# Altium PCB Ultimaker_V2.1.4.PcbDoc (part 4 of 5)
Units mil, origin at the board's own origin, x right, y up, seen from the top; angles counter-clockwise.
Board outline 6889.76 x 3110.24 mil, 4 copper layers (top, signal, Power, bot (thermal)), stack 67.717 mil thick; 574 components, 252 nets, 1322 pads, 511 vias.
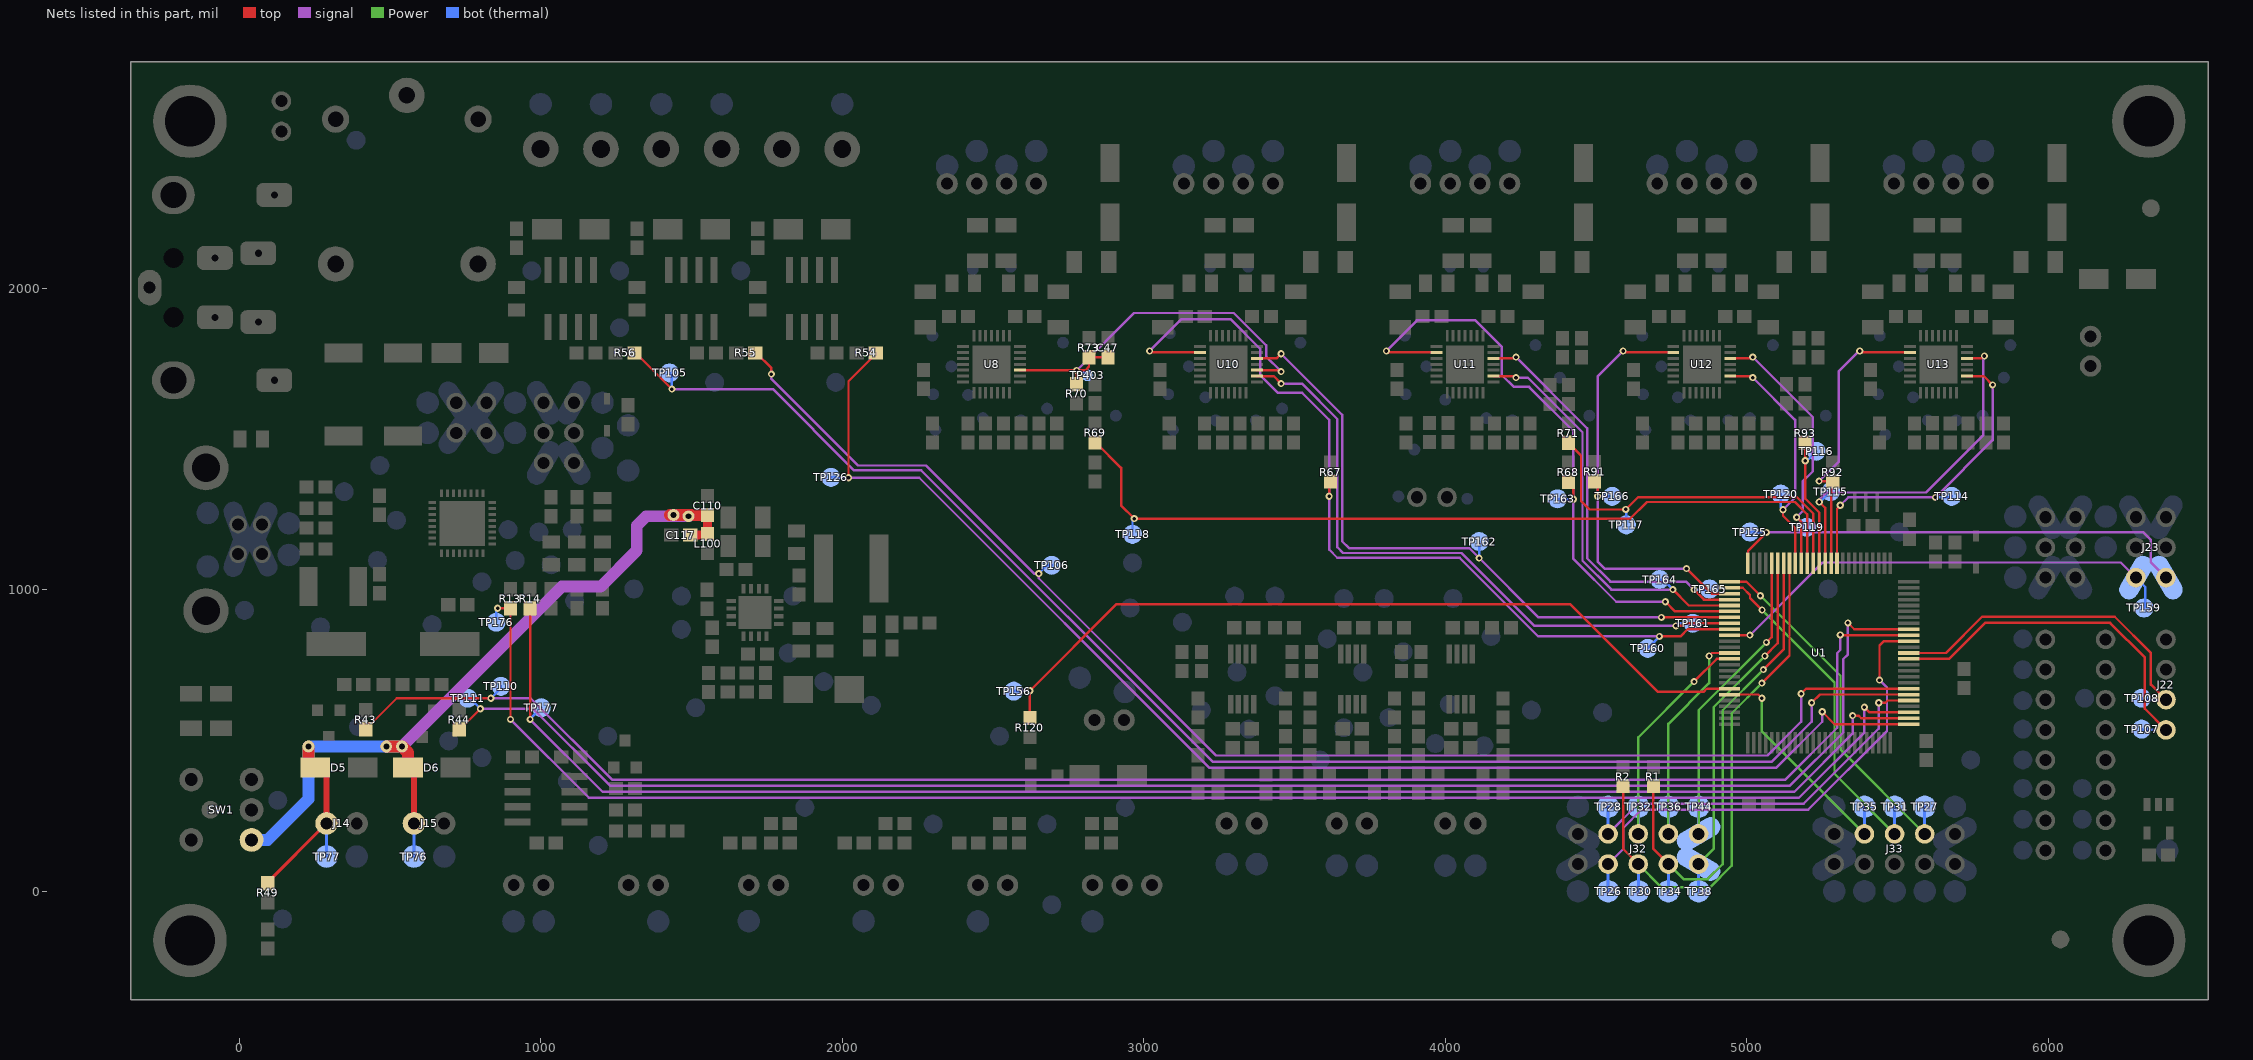
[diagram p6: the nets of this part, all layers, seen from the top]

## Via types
v1: diameter 23.62, hole 11.81, top to bot (thermal), tented bottom, 172 vias
v2: diameter 23.62, hole 11.81, top to bot (thermal), tented both sides, 104 vias
v3: diameter 39.37, hole 19.68, top to bot (thermal), tented bottom, 88 vias
v4: diameter 25.98, hole 12.99, top to bot (thermal), tented bottom, 58 vias
v5: diameter 23.62, hole 11.81, top to bot (thermal), 46 vias
v6: diameter 39.37, hole 19.68, top to bot (thermal), tented both sides, 43 vias

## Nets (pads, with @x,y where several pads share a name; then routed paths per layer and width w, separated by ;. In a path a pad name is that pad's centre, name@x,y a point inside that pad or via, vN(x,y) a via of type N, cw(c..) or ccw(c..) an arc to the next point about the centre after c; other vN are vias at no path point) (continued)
PC0: R91.1 TP166.1 U1.53 U12.2 | length 1469.7
  top w8: v1(4505,1309.88) R91.1@4505,1349.88 ; v1@4590.27,1786.76 U12.2@4756.14,1786.76 ; v1(4800,1070) 4883.15,986.85 U1.53@4942.76,986.85
  signal w8: v1(4589.64,1791.39) 4505,1706.76 v1(4505,1309.88) 4505,1093.03 4528.03,1070 v1(4800,1070)
  bot (thermal) w8: v1(4505,1309.88) 4552.8,1309.88 TP166.1@4553.39,1309.29
PC1: TP165.1 U1.54 U11.19 | length 1422.5
  top w8: U11.19@4160.12,1767.08 4230.32,1767.08 v1(4234.64,1771.39) ; v1(4825,1000) 4857.83,967.17 U1.54@4942.76,967.17
  signal w8: v1(4234.64,1771.39) 4471,1535.03 4471,1103.4 4547.48,1026.92 4798.08,1026.92 v1(4825,1000)
  bot (thermal) w8: v1(4825,1000) 4874.02,1000 TP165.1@4876.22,1002.2
PC2: TP164.1 U1.55 U11.16 | length 1405.3
  top w8: U11.16@4160.12,1708.02 4230.01,1708.02 v1(4234.64,1703.39) ; v1(4755,1000) 4807.52,947.48 U1.55@4942.76,947.48
  signal w8: v1(4234.64,1703.39) 4273.46,1703.39 4455,1521.85 4455,1095.78 4550.78,1000 v1(4755,1000)
  bot (thermal) w8: TP164.1@4710.87,1033.7 4721.3,1033.7 v1(4755,1000)
PC3: R68.1 TP163.1 U1.56 U11.2 | length 2182.5
  top w8: v1@3805.27,1786.76 U11.2@3971.14,1786.76 ; R68.1@4420,1354.88 4416.5,1358.39 4405,1358.39 4425,1338.39 v1(4425,1299.88) ; v1(4730,960) 4762.2,927.8 U1.56@4942.76,927.8
  signal w8: v1@3804.64,1791.52 3906,1892.88 4100,1892.88 4187,1805.88 4187,1712.88 4227.49,1672.39 4277.89,1672.39 4425,1525.29 v1(4425,1299.88) 4425,1102.16 4567.16,960 v1(4730,960)
  bot (thermal) w8: TP163.1@4373.82,1299.88 v1(4425,1299.88)
  other v1: 3804.64,1791.39
PC4: TP162.1 U1.57 U10.19 | length 2234.9
  top w8: U10.19@3375.12,1767.08 3440.32,1767.08 3450.64,1777.39 v1@3455.64,1777.39 ; v1(4716.69,908.11) U1.57@4942.76,908.11
  signal w8: v1(3455.64,1782.39) 3657.97,1580.06 3657.97,1160.53 3680.84,1137.66 4079.35,1137.66 v5(4112.44,1104.57) 4308.9,908.11 v1(4716.69,908.11)
  bot (thermal) w8: v5(4112.44,1104.57) TP162.1@4112.44,1159.69
PC5: TP161.1 U1.58 U10.16 | length 2222.6
  top w8: U10.16@3375.12,1708.02 3431.01,1708.02 v1(3455.64,1683.39) ; v1(4765,880) 4785.2,880 4793.62,888.43 U1.58@4942.76,888.43
  signal w8: v1(3455.64,1683.39) 3524.64,1683.39 3641.97,1566.06 3641.97,1141.09 3661.4,1121.66 4054.11,1121.66 4295.77,880 v1(4765,880)
  bot (thermal) w8: v1(4765,880) 4773.43,888.43 TP161.1@4821.1,888.43
PC6: R67.1 TP160.1 U1.59 U10.2 | length 2983.8
  top w8: v1@3020.27,1786.76 U10.2@3186.14,1786.76 ; v1(3615,1309.88) R67.1@3615,1353.39 ; v1(4710,845) 4715,850 4720,845 4780,845 4803.74,868.74 U1.59@4942.76,868.74
  signal w8: v1(3019.64,1791.39) 3125.64,1897.39 3287.64,1897.39 3386.07,1798.97 3386.07,1711.97 3445.64,1652.39 3525.64,1652.39 3615,1563.03 v1(3615,1309.88) 3615,1132.63 3641.97,1105.66 4047.48,1105.66 4308.14,845 v1(4710,845)
  bot (thermal) w8: TP160.1@4671.5,806.5 v1(4710,845)
PC7: J23.2@6290,1040 J23.5 TP159.1 U1.60 | length 1583.1
  top w8: U1.60@4942.76,849.06 v1(5010,849.06)
  signal w8: v1(5010,849.06) 5250.94,1090 6240,1090 J23.5@6290,1040
  bot (thermal) w8: J23.5@6290,1040 6321.1,1008.9 6321.1,943.15 TP159.1@6317.17,939.21
PD7: J23.4@6390,1040 J23.6 TP125.1 U1.50 | length 1624.6
  top w8: U1.50@5003.78,1077.24 U1.50@5003.78,1087.24 5003.78,1128.78 v1(5065,1190)
  signal w8: v1(5065,1190) 6315,1190 6340,1165 6340,1090 J23.6@6390,1040
  bot (thermal) w8: TP125.1@5010.08,1191.18 5011.26,1190 v1(5065,1190)
PE0: R14.2 TP177.1 U1.2 | length 5237.6
  top w8: v1(965,570) R14.2@965,938.5 ; v1(5350.64,582.51) 5370.64,582.51 5379.68,573.46 U1.2@5537.24,573.46
  signal w8: v1(965,570) 1205,330 5158.13,330 5350.64,522.51 v1(5350.64,582.51)
  bot (thermal) w8: v1(965,570) 965,571.3 TP177.1@1002.2,608.5
PE1: R13.2 TP176.1 U1.3 | length 5384.6
  top w8: v2(857.24,938.5) R13.2@900,938.5 v1(900,570) ; v1(5390,610) 5406.85,593.15 U1.3@5537.24,593.15
  signal w8: v1(900,570) 1160,310 5173.13,310 5390,526.87 v1(5390,610)
  bot (thermal) w8: TP176.1@852.6,891.97 852.6,933.86 v2(857.24,938.5)
PE3: J32.7 TP28.1 U1.5 | length 1320.7
  top w8: v1(5437.5,625) 5460,625 5467.52,632.52 U1.5@5537.24,632.52
  signal w8: J32.7@4540,190 4640,290 5188.13,290 5437.5,539.37 v1(5437.5,625)
  bot (thermal) w10: J32.7@4540,190 TP28.1@4540,280
PE4: R56.1 TP105.1 U1.6 | length 4965.9
  top w8: R56.1@1317.5,1782.5 v1(1435,1665) ; v1(5215,625) 5242.2,652.2 U1.6@5537.24,652.2
  signal w8: v1(1435,1665) 1770,1665 2039.35,1395.65 2262.3,1395.65 3227.95,430 5083.13,430 5215,561.87 v1(5215,625)
  bot (thermal) w8: TP105.1@1427.4,1718.74 1435,1711.14 v1(1435,1665)
PE5: R55.1 TP106.1 U1.7 | length 4615.5
  top w8: R55.1@1711.5,1785 1715,1785 1765,1735 v1(1765,1715) ; v1(5180,655) 5196.89,671.89 U1.7@5537.24,671.89
  signal w8: v1@1765,1710 v1(1765,1715) 1765,1698.5 2051.85,1411.65 2277.8,1411.65 2636.06,1053.39 v5(2651.81,1053.39) 2651.81,1037.64 3239.45,450 5068.13,450 5180,561.87 v1(5180,655)
  bot (thermal) w8: v5(2651.81,1053.39) 2679.37,1080.94 TP106.1@2695.12,1080.94
PG0: J33.3 TP27.1 U1.51 | length 1239.4
  top w8: U1.51@4955,1026.22 U1.51@4942.76,1026.22 4998.78,1026.22 v1(5045,980)
  Power w8: v1(5045,980) 5310.64,714.36 5310.64,469.36 J33.3@5590,190
  bot (thermal) w10: J33.3@5590,190 TP27.1@5590,280
PG1: J33.5 TP31.1 U1.52 | length 1158.9
  top w8: U1.52@4942.76,1006.54 4986.61,1006.54 5010.64,982.51 5010.64,972.51 v1(5050.64,932.51)
  Power w8: v1(5050.64,932.51) 5290.64,692.51 5290.64,389.36 J33.5@5490,190
  bot (thermal) w10: J33.5@5490,190 TP31.1@5490,280
PG2: J33.7 TP35.1 U1.70 | length 793.1
  top w8: U1.70@4942.76,652.2 5037.8,652.2 v1(5050,640)
  Power w8: v1(5050,640) 5050,530 J33.7@5390,190
  bot (thermal) w10: J33.7@5390,190 TP35.1@5390,280
PG5: R54.1 TP126.1 U1.1 | length 4538
  top w8: v1(2021,1371) 2021,1691 R54.1@2112.5,1782.5 ; R54.1@2111.5,1785 R54.1@2113.25,1783.25 ; v1(5250,595) 5291.22,553.78 U1.1@5537.24,553.78
  signal w8: v1(2021,1371) 2255.46,1371 3216.46,410 5098.13,410 5250,561.87 v1(5250,595)
  bot (thermal) w8: TP126.1@1962.83,1372.28 2019.72,1372.28 v1(2021,1371)
PH3: J32.8 TP26.1 U1.15 | length 1635.7
  top w8: v1(5440,700) 5440,815 5454.37,829.37 U1.15@5537.24,829.37
  signal w8: J32.8@4540,90 4590,140 4590,210 4650,270 5203.13,270 5465,531.87 5465,675 v1(5440,700)
  bot (thermal) w10: TP26.1@4540,0 J32.8@4540,90
PH4: R43.1 TP110.1 U1.16 | length 5698.4
  top w8: R43.1@420,537.01 523,640 v1(835,640) ; v1@5310,849.06 U1.16@5537.24,849.06
  signal w8: v1(835,640) 966.77,640 1236.77,370 5128.13,370 5300,541.87 5300,790 5310,800 v1(5310,850)
  bot (thermal) w8: v1(835,640) 868.35,673.35 TP110.1@868.35,679.37
PH5: R44.1 TP111.1 U1.17 | length 5433.8
  top w8: R44.1@732.01,537.01 v1(800,605) ; v1(5335,890) 5356.26,868.74 U1.17@5537.24,868.74
  top w10: R44.1@730,537.01 R44.1@732.01,537.01
  signal w8: v1(800,605) 975,605 1230,350 5143.13,350 5320,526.87 5320,770 5335,785 v1(5335,890)
  bot (thermal) w8: TP111.1@765,640 v1(800,605) v1@793.11,605
PJ6: R120.1 TP156.1 U1.69 | length 2709
  top w8: R120.1@2622.29,574.17 v5(2622.29,664.72) 2909.69,952.12 4413.62,952.12 4704.96,660.78 4855.97,660.78 4867.08,671.89 U1.69@4942.76,671.89
  bot (thermal) w8: TP156.1@2569.13,663.62 2570.23,664.72 v5(2622.29,664.72)
PL0: TP114.1 U1.35 U13.16 | length 1133.3
  top w8: U1.35@5299.06,1087.24 5299.06,1268.06 v1@5310.5,1279.5 ; U13.16@5730.12,1708.02 5785.86,1708.02 v1(5815,1678.88)
  signal w8: v1(5310,1280) 5336.2,1306.2 v5(5625.32,1306.2) 5815,1495.88 v1(5815,1678.88)
  bot (thermal) w8: v5(5625.32,1306.2) 5676.28,1306.2 TP114.1@5679.37,1309.29 ; v1(5815,1678.88) v1@5821.59,1678.88
PL1: R92.1 U1.36 U13.2 | length 970
  top w8: v1(5240,1359.88) R92.1@5285,1359.88 ; U1.36@5279.37,1087.24 5279.37,1352.76 R92.1@5285,1358.39 ; v1@5375.27,1786.76 U13.2@5541.14,1786.76
  signal w8: v1(5240,1359.88) 5305.35,1425.24 5305.35,1724.93 v1@5369.99,1789.57 ; v1@5374.63,1791.08 v1@5376.14,1789.57
  other v1: 5374.64,1791.39
PL2: TP115.1 U1.37 U13.19 | length 1204.4
  top w8: v5(5240.4,1290.7) 5259.68,1271.41 U1.37@5259.68,1087.24 U1.37@5260,1087.56 ; U13.19@5730.12,1767.08 v1@5779.77,1767.08
  signal w8: v5@5240.4,1298.57 5264.02,1322.2 5594.73,1322.2 5783.7,1511.17 v1@5783.7,1771.02
  bot (thermal) w8: v5(5240.4,1290.7) 5243.46,1290.7 TP115.1@5277.8,1325.04
  other v1: 5787.64,1774.95
PL3: R93.1 TP116.1 U1.38 | length 469.8
  top w8: R93.1@5193.64,1487.9 v2(5193.64,1427.4) 5193.64,1302.03 5240,1255.66 U1.38@5240,1087.24
  bot (thermal) w8: v2(5193.64,1427.4) 5199.05,1427.4 TP116.1@5230.55,1458.9
PL4: R71.1 TP117.1 U1.39 | length 1251.4
  top w8: R71.1@4405.64,1488.39 4406.49,1488.39 4450,1444.88 4450,1294.57 4478.58,1265.98 v2(4598.56,1265.98) 4639.28,1306.7 5165.93,1306.7 5220.32,1252.31 U1.39@5220.32,1087.24
  bot (thermal) w8: v2(4598.56,1265.98) 4600.63,1263.92 TP117.1@4600.63,1214.8
PL5: R69.1 TP118.1 U1.40 | length 2799.6
  top w8: R69.1@2835.64,1488.39 2840.64,1488.39 2925,1404.03 2925,1279.33 v2(2968.74,1235.58) 4613.54,1235.58 4668.65,1290.7 5159.3,1290.7 5200,1250 5200,1087.87 U1.40@5200.63,1087.24
  bot (thermal) w8: TP118.1@2962.83,1183.31 2962.83,1229.67 v2(2968.74,1235.58)
PL6: TP119.1 U1.41 U12.19 | length 919.5
  top w8: U12.19@4945.12,1767.08 5015.32,1767.08 v1(5019.64,1771.39) ; v2(5165,1240) 5180.94,1224.06 U1.41@5180.94,1087.24
  signal w8: v1(5019.64,1771.39) 5218.74,1572.29 5218.74,1391.97 5185,1358.23 5185,1260 v2(5165,1240)
  bot (thermal) w8: v2(5165,1240) 5165.98,1240 TP119.1@5199.06,1206.93
PL7: TP120.1 U1.42 U12.16 | length 833.1
  top w8: U12.16@4945.12,1708.02 v1@5015.01,1708.02 ; v2(5120,1265) 5120,1245 5161.26,1203.74 U1.42@5161.26,1087.24
  signal w8: v1(5019.64,1703.39) 5160,1563.03 5160,1305 v2(5120,1265)
  bot (thermal) w8: TP120.1@5112.44,1317.17 5112.44,1272.56 v2(5120,1265)
RXD1: J32.2 TP38.1 U1.45 | length 1195.9
  top w8: v1(5060,780) 5102.2,822.2 U1.45@5102.2,1087.24
  Power w8: J32.2@4840,90 4890,140 4890,610 v1(5060,780)
  bot (thermal) w10: TP38.1@4840,0 J32.2@4840,90
RXD2: J22.4 TP107.1 U1.12 | length 1230.8
  top w8: U1.12@5537.24,770.31 5670.32,770.31 5790,890 6205,890 6320,775 6320,605 J22.4@6390,535
  bot (thermal) w8: TP107.1@6309.29,537.64 6311.93,535 J22.4@6390,535
RXD3: J32.3 TP36.1 U1.63 | length 807.8
  top w8: v1(4875,780) 4885,790 U1.63@4942.76,790
  Power w8: J32.3@4740,190 4740,555 4875,690 v1(4875,780)
  bot (thermal) w10: J32.3@4740,190 TP36.1@4740,280
SCL: J32.6 R2.2 TP30.1 U1.43 | length 1822.9
  top w8: R2.2@4590,348.5 4590,140 J32.6@4640,90 ; v1(5050,690) 5141.57,781.57 U1.43@5141.57,1087.24
  Power w8: J32.6@4640,90 4717.49,12.51 4877.51,12.51 4950,85 4950,590 v1(5050,690)
  bot (thermal) w10: TP30.1@4640,0 J32.6@4640,90
SDA: J32.4 R1.2 TP34.1 U1.44 | length 1671.5
  top w8: R1.2@4690,348.5 4690,140 J32.4@4740,90 ; v1(5055,735) 5121.89,801.89 U1.44@5121.89,1087.24
  Power w8: J32.4@4740,90 4790,40 4870,40 4920,90 4920,600 v1(5055,735)
  bot (thermal) w10: TP34.1@4740,0 J32.4@4740,90
TXD1: J32.1 TP44.1 U1.46 | length 1087.7
  top w8: v1(5065,825) 5082.52,842.52 U1.46@5082.52,1087.24
  Power w8: J32.1@4840,190 4840,600 v1(5065,825)
  bot (thermal) w10: J32.1@4840,190 TP44.1@4840,280
TXD2: J22.3 TP108.1 U1.13 | length 1160.7
  top w8: U1.13@5537.24,790 5660,790 5780,910 6220,910 6340,790 6340,685 J22.3@6390,635
  bot (thermal) w8: TP108.1@6309.29,640 6314.29,635 J22.3@6390,635
TXD3: J32.5 TP32.1 U1.64 | length 820.6
  top w8: v1(4825,695) 4900.32,770.31 U1.64@4942.76,770.31
  Power w8: J32.5@4640,190 4640,510 v1(4825,695)
  bot (thermal) w10: J32.5@4640,190 TP32.1@4640,280
VCC/2: C110.2 C117.2 D5.2 D6.2 J14.1 J15.1 L100.1 R49.2 SW1.1 TP76.1 TP77.1 | length 3463.4
  top w10: R49.2@91.5,26.5 J14.1@290,225 J14.1@290,230
  top w20: D5.2@252.52,410 290,410 J14.1@290,230 ; v3(488.19,480.31) v3@488.5,480 ; D6.2@560,410 580,390 J15.1@580,230
  top w30: C117.2@1496.06,1181.1 1550.09,1181.1 L100.1@1553.39,1184.4 C110.2@1553.39,1247.39
  top w40: D5.2@230,410 v3(230,480) ; v3@488.5,480 540,480 560,460 D6.2@560,410 ; v6@1429.13,1247.39 C110.2@1553.39,1247.39
  signal w39.37: v3(488.19,480.31) v3@540,480.31 ; v3@540.31,480.31 1070,1010 1198.98,1010 1318.9,1129.92 1318.9,1212.6 1349.76,1243.46 1441.18,1243.46 v6(1490.4,1243.46)
  bot (thermal) w10: TP77.1@290,115 J14.1@290,230 ; TP76.1@580,115 J15.1@580,230
  bot (thermal) w39.37: SW1.1@41.26,170 95,170 230,305 v3(230,480) v3@539.69,480
  other v3: 539.69,480.31
  other v6: 1440.94,1247.39
YREF: C47.2 R70.2 R73.2 TP403.1 U8.17 U10.17 | length 1356
  top w8: U8.17@2590.13,1727.71 2777.64,1727.71 v1(2777.64,1727.39) ; R70.2@2777.64,1685.89 v1(2777.64,1727.39) ; R73.2@2818.47,1771.02 2818.47,1739.52 2806.35,1727.39 v1(2777.64,1727.39) ; R73.2@2818.47,1771.39 C47.2@2881.46,1771.39 ; U10.17@3375.12,1727.71 3448.32,1727.71 v1@3454.64,1721.39
  signal w8: v1(2777.64,1727.39) 2967.64,1917.39 3298.74,1917.39 3405.75,1810.39 3405.75,1773.28 v1@3454.64,1724.39 ; v1@3454.64,1721.39 v1@3454.64,1724.39 ; v1(3455.64,1723.39) v1@3454.64,1724.39
  bot (thermal) w8: v1(2777.64,1727.39) 2796.7,1727.39 TP403.1@2813.23,1710.87
pads on no net: Fid1. Fid2. Fid3. J18.0 K1.5 SP1.0 SP2.0 SP3.0 SP4.0 SW1.0 SW1.3 U1.4 U1.8 U1.9 U1.14 U1.18 U1.23 U1.24 U1.25 U1.27 U1.28 U1.29 U1.47 U1.48 U1.49 U1.65 U1.66 U1.67 U1.68 U1.76 U1.79 U2.5 U2.6 U2.7 U2.12 U2.14 U2.22 U2.23 U2.25 U2.26 U7.7 U8.7 U8.20 U8.25 U9.4 U10.7 U10.20 U10.25 U11.7 U11.20 U11.25 U12.7 U12.20 U12.25 U13.7 U13.20 U13.25

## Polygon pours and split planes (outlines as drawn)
+5V on Power "+5V" (solid, remove dead copper, pour order 16): 6500,2390 6170,2390 6170,2720 0,2720 0,2390 -330,2390 -330,0 0,0 0,-330 6170,-330 6170,0 6500,0
GND on signal "+5V" (solid, remove dead copper, pour order 15): 6500,2390 6170,2390 6170,2720 0,2720 0,2390 -330,2390 -330,0 0,0 0,-330 6170,-330 6170,0 6500,0
+24V on signal "Top Layer-No Net 1" (solid, pour order 17): 5413.63,2092.39 5413.63,1935.39 5580.63,1935.39 5580.63,1967.39 5455.63,2092.39 5413.63,2092.39
+24V on signal "Top Layer-No Net 1" (solid, pour order 22): 5690.63,1935.39 5690.63,1967.39 5815.63,2092.39 5905.98,1966.77 5815.63,1935.39
+24V on signal "Top Layer-No Net 1" (solid, pour order 18): 4628.63,2092.39 4628.63,1935.39 4795.63,1935.39 4795.63,1967.39 4670.63,2092.39 4628.63,2092.39
+24V on signal "Top Layer-No Net 1" (solid, pour order 23): 4905.63,1935.39 4905.63,1967.39 5030.63,2092.39 5120.98,1966.77 5030.63,1935.39
+24V on signal "Top Layer-No Net 1" (solid, pour order 19): 3843.63,2092.39 3843.63,1935.39 4010.63,1935.39 4010.63,1967.39 3885.63,2092.39 3843.63,2092.39
+24V on signal "Top Layer-No Net 1" (solid, pour order 24): 4120.63,1935.39 4120.63,1967.39 4245.63,2092.39 4335.98,1966.77 4245.63,1935.39
+24V on signal "Top Layer-No Net 1" (solid, pour order 20): 3058.63,2092.39 3058.63,1935.39 3225.63,1935.39 3225.63,1967.39 3100.63,2092.39 3058.63,2092.39
+24V on signal "Top Layer-No Net 1" (solid, pour order 25): 3335.63,1935.39 3335.63,1967.39 3460.63,2092.39 3550.98,1966.77 3460.63,1935.39
+24V on signal "Top Layer-No Net 1" (solid, pour order 26): 2550.64,1935.39 2550.64,1967.39 2675.64,2092.39 2765.98,1966.77 2675.64,1935.39
+24V on signal "Top Layer-No Net 1" (solid, pour order 21): 2273.64,2092.39 2273.64,1935.39 2440.64,1935.39 2440.64,1967.39 2315.64,2092.39 2273.64,2092.39
GND on bot (thermal) "GND" (solid, remove dead copper, pour order 14): -330,2395 -5,2395 -5,2720 6170,2720 6170,2390 6500,2390 6500,0 6170,0 6170,-330 0,-329.51 0,0 -330,0

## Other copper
top:
  rectangle net +5V: 2165.59,672.59 2311.26,771.02
  region net +24V: 2889.12,2038.71 2889.12,2039.16 2914.22,2038.87 2920.22,2038.87 2920.22,1967.87 2811.22,1967.87 2811.22,2038.87 2864.22,2038.87
  region net +24V: 6120.63,2506.39 6120.63,2192.39 6084.63,2156.39 6058.63,2156.39 6058.63,2281.39 6069.63,2292.39 6069.63,2506.39
  region net +24V: 6029.11,2038.71 6029.11,2039.16 6054.21,2038.87 6060.21,2038.87 6060.21,1967.87 5951.21,1967.87 5951.21,2038.87 6004.21,2038.87
  region net +24V: 5334.88,2566.29 5335.63,2192.39 5299.63,2156.39 5273.63,2156.39 5273.63,2281.39 5284.63,2292.39 5283.7,2566.29
  region net +24V: 5244.11,2038.71 5244.11,2039.16 5269.21,2038.87 5275.21,2038.87 5275.21,1967.87 5166.21,1967.87 5166.21,2038.87 5219.21,2038.87
  region net +24V: 4551.42,2570.23 4550.63,2192.39 4514.63,2156.39 4488.63,2156.39 4488.63,2281.39 4499.63,2292.39 4499.63,2506.39 4500.24,2570.23
  region net +24V: 4459.11,2038.71 4459.11,2039.16 4484.21,2038.87 4490.21,2038.87 4490.21,1967.87 4381.21,1967.87 4381.21,2038.87 4434.21,2038.87
  region net +24V: 3764.02,2570.23 3765.63,2192.39 3729.63,2156.39 3703.63,2156.39 3703.63,2281.39 3714.63,2292.39 3712.84,2570.23
  region net +24V: 3674.11,2038.71 3674.11,2039.16 3699.21,2038.87 3705.21,2038.87 3705.21,1967.87 3596.21,1967.87 3596.21,2038.87 3649.21,2038.87
  region net NetL160_1: 5748.63,1810.39 5796.63,1810.39 5820.67,1834.01 5820.67,1849.76 5875.79,1849.76 5875.79,1822.2 5851.63,1807.39 5845.63,1802.39 5748.63,1802.39
  region net NetL150_1: 4963.63,1810.39 5011.63,1810.39 5035.67,1834.01 5035.67,1849.76 5090.79,1849.76 5090.79,1822.2 5066.63,1807.39 5060.63,1802.39 4963.63,1802.39
  region net NetL140_1: 4178.63,1810.39 4226.63,1810.39 4250.67,1834.01 4255.91,1850.39 4305.79,1849.76 4305.79,1822.2 4281.63,1807.39 4275.63,1802.39 4178.63,1802.39
  region net GND: 5879.73,2475.74 5997.84,2475.74 6000.63,2352.39 5941.18,2353.69 5941.18,1956.06 6086.85,1956.06 6088.39,1692.28 6007.54,1692.28 5874.92,1692.28 5870.99,1696.21 5826.63,1743.39 5826.63,1751.39 5897.64,1818.9 5897.64,2023.62 5881.89,2023.62
  region net GND: 5094.73,2475.74 5212.84,2475.74 5215.63,2352.39 5151.7,2352.39 5153.78,1956.06 5303.39,1956.06 5303.39,1692.28 5222.54,1692.28 5220.63,1693.39 5220.63,1703.39 5220.71,1735.58 5267.96,1735.58 5267.96,1865.5 5141.97,1865.5 5141.97,1767.08 5118.35,1743.46 5070.63,1743.39 5041.63,1743.39 5041.63,1751.39 5118.11,1826.77 5118.11,2023.62 5094.49,2023.62
  region net GND: 4309.73,2475.74 4427.84,2475.74 4430.63,2352.39 4370.63,2352.39 4370.32,1956.06 4515.99,1956.06 4518.39,1692.28 4437.54,1692.28 4435.63,1693.39 4435.63,1703.39 4435.71,1735.58 4437.25,1735.58 4484.49,1735.58 4484.49,1865.5 4356.97,1865.5 4356.97,1767.08 4333.35,1743.46 4285.63,1743.39 4256.63,1743.39 4256.63,1751.39 4317.6,1814.32 4338.58,1838.58 4338.58,2023.62 4307.09,2023.62
  region net GND: 3524.73,2475.74 3642.84,2475.74 3645.63,2352.39 3586.85,2353.69 3586.85,1956.06 3732.52,1956.06 3733.39,1692.28 3652.54,1692.28 3519.92,1692.28 3515.99,1696.21 3471.63,1743.39 3471.63,1751.39 3532.6,1814.32 3551.18,1830.71 3551.18,2023.62 3527.56,2023.62
  region net NetL130_1: 3393.63,1810.39 3441.63,1810.39 3465.67,1834.01 3465.67,1849.76 3468.5,1854.33 3520.79,1849.76 3520.79,1822.2 3496.63,1807.39 3490.63,1802.39 3393.63,1802.39
  region net GND: 5739.63,2293.39 5728.63,2293.39 5728.63,2232.39 5724.41,2204.72 5724.41,2090.55 5759.84,2090.55 5759.84,2055.12 5746,2044 5788,2044 5800.99,2054.48 5800.99,2172.59 5739.63,2232.39
  region net GND: 4954.63,2293.39 4943.63,2293.39 4943.63,2232.39 4944.88,2228.35 4944.88,2090.55 4980.32,2090.55 4980.32,2055.12 4962,2043 5003,2043 5015.99,2054.48 5015.99,2172.59 4954.63,2232.39
  region net GND: 4169.63,2293.39 4158.63,2293.39 4157.48,2244.09 4165.35,2244.09 4165.35,2090.55 4200.79,2090.55 4200.79,2055.12 4181.1,2039.37 4216.54,2039.37 4230.99,2054.48 4230.99,2172.59 4169.63,2232.39
  region net GND: 3384.63,2293.39 3373.63,2293.39 3374.02,2244.09 3377.95,2244.09 3377.95,2090.55 3413.39,2090.55 3413.39,2055.12 3397,2044 3433,2044 3445.99,2054.48 3445.99,2172.59 3384.63,2232.39
  region net NetL163_1: 5522.63,1810.39 5474.22,1810.39 5450.59,1837.94 5450.59,1857.63 5395.48,1857.63 5395.48,1830.07 5419.63,1808.39 5425.63,1802.39 5522.63,1802.39
  region net NetL153_1: 4737.63,1810.39 4689.22,1810.39 4665.59,1837.94 4665.59,1857.63 4610.48,1857.63 4610.48,1830.07 4634.63,1808.39 4640.63,1802.39 4737.63,1802.39
  region net NetL143_1: 3952.63,1810.39 3904.22,1810.39 3880.59,1837.94 3880.59,1857.63 3825.48,1857.63 3825.48,1830.07 3849.63,1808.39 3855.63,1802.39 3952.63,1802.39
  region net GND: 5531.63,2293.39 5542.63,2293.39 5542.63,2232.39 5543.31,2224.41 5543.31,2090.55 5507.87,2090.55 5507.87,2051.18 5526,2044 5483,2044 5478.15,2050.54 5479.63,2180.39 5531.63,2232.39
  region net GND: 4746.63,2293.39 4757.63,2293.39 4757.63,2232.39 4755.91,2224.41 4755.91,2090.55 4720.47,2090.55 4720.47,2051.18 4736,2043 4699,2043 4693.15,2050.54 4694.63,2180.39 4746.63,2232.39
  region net GND: 3961.63,2293.39 3972.63,2293.39 3972.63,2232.39 3980.32,2220.47 3980.32,2090.55 3944.88,2090.55 3944.88,2051.18 3955,2044 3913,2044 3908.15,2050.54 3909.63,2180.39 3961.63,2232.39
  region net GND: 5409.64,2293.39 5409.45,2023.62 5370.08,2023.62 5370.08,1814.96 5349.64,1814.39 5349.64,1771.39 5377.64,1771.39 5377.64,1627.39 5407.64,1627.39 5407.64,1454.39 5471.64,1454.39 5471.64,1501.39 5524.64,1501.39 5524.64,1419.39 5883.64,1419.39 5883.64,1520.39 5936.64,1520.39 5936.64,1347.39 5425.44,1345.82 5425.44,1369.44 5327.01,1369.44 5325.63,2146.39 5345.63,2146.39 5345.63,2293.39
  region net GND: 4624.64,2293.39 4626.22,2046.61 4625.98,2039.37 4582.68,2023.62 4582.68,1814.96 4564.64,1814.39 4564.64,1771.39 4592.64,1771.39 4592.64,1627.39 4622.64,1627.39 4622.64,1454.39 4686.64,1454.39 4686.64,1501.39 4739.64,1501.39 4739.64,1419.39 5098.64,1419.39 5098.64,1520.39 5151.64,1520.39 5151.64,1347.39 4540.64,1347.39 4540.63,2146.39 4560.63,2146.39 4560.63,2293.39
  region net GND: 3834.65,2291.34 3838.58,2047.24 3829.41,2046.61 3803.15,2019.69 3803.15,1988.19 3801.85,1814.32 3779.64,1814.39 3779.64,1771.39 3807.64,1771.39 3807.64,1627.39 3837.64,1627.39 3837.64,1454.39 3838.58,1417.32 3897.64,1417.32 3901.57,1421.26 4313.64,1419.39 4313.64,1520.39 4366.64,1520.39 4366.64,1347.39 3755.64,1347.39 3755.63,2146.39 3775.63,2146.39 3775.59,2291.34
  region net NetL120_1: 2608.64,1810.39 2656.64,1810.39 2680.68,1834.01 2680.68,1849.76 2735.8,1849.76 2735.8,1822.2 2711.64,1807.39 2705.64,1802.39 2608.64,1802.39
  region net NetL123_1: 2382.64,1810.39 2334.22,1810.39 2310.6,1837.94 2310.6,1857.63 2255.48,1857.63 2255.48,1830.07 2279.64,1808.39 2285.64,1802.39 2382.64,1802.39
  region net GND: 2391.64,2293.39 2402.64,2293.39 2401.57,2291.34 2401.57,2090.55 2366.14,2090.55 2366.14,2051.18 2384,2043 2342.52,2043.31 2338.16,2050.54 2339.64,2180.39 2391.64,2232.39
  region net GND: 2599.64,2293.39 2588.64,2293.39 2588.64,2232.39 2590.55,2220.47 2590.55,2090.55 2625.98,2090.55 2625.98,2055.12 2608,2043 2647,2043 2660.99,2054.48 2660.99,2172.59 2599.64,2232.39
  region net GND: 2267.72,2291.34 2267.72,2023.62 2228.35,2023.62 2228.35,1814.96 2209.64,1814.39 2209.64,1771.39 2237.64,1771.39 2237.64,1627.39 2267.64,1627.39 2267.64,1454.39 2331.64,1454.39 2331.64,1501.39 2384.64,1501.39 2384.64,1419.39 2743.64,1419.39 2743.64,1520.39 2796.64,1520.39 2796.64,1347.39 2185.64,1347.39 2185.04,2291.34
  region net GND: 2739.73,2475.74 2857.84,2475.74 2860.64,2352.39 2799.45,2353.69 2799.45,1956.06 2949.06,1956.06 2948.39,1692.28 2867.54,1692.28 2865.64,1693.39 2865.64,1703.39 2865.72,1735.58 2866.38,1735.58 2913.62,1735.58 2912.96,1865.5 2786.98,1865.5 2786.98,1767.08 2763.35,1743.46 2715.64,1743.39 2686.64,1743.39 2686.64,1751.39 2763.78,1830.71 2763.78,2023.62 2740.16,2023.62
  region net +24V: 2980.55,2566.29 2980.64,2192.39 2944.64,2156.39 2918.64,2156.39 2918.64,2281.39 2929.64,2292.39 2929.64,2506.39 2929.37,2566.29
  region net GND: 3051.18,2291.34 3051.18,2047.24 3015.75,2047.24 3015.75,1814.96 2994.64,1814.39 2994.64,1771.39 3022.64,1771.39 3022.64,1627.39 3052.64,1627.39 3052.64,1454.39 3116.64,1454.39 3116.64,1501.39 3169.64,1501.39 3169.64,1419.39 3528.64,1419.39 3528.64,1520.39 3581.64,1520.39 3581.64,1347.39 2970.64,1347.39 2970.63,2146.39 2990.63,2146.39 2992.13,2291.34
  region net HEATER1: 1120,2500 1160,2540 1240,2540 1280,2500 1280,2270 1240,2230 1240,2030 1200,1990 1000,1990 1000,2120 1120,2120
  region net HEATER2: 1520,2500 1560,2540 1640,2540 1680,2500 1680,2270 1640,2230 1640,2030 1600,1990 1400,1990 1400,2120 1520,2120
  region net HEATED-BED: 1920,2500 1960,2540 2040,2540 2080,2500 2080,2270 2040,2230 2040,2030 2000,1990 1800,1990 1800,2120 1920,2120
  region net +24V: 6120.63,2682.51 6120.64,2247.51 6084.64,2211.51 6058.64,2211.51 6058.64,2336.51 6069.64,2347.51 6069.63,2561.51 6035.63,2561.51 6035.63,2726.51 6076.63,2726.51
  region net NetL133_1: 3167.63,1810.39 3119.22,1810.39 3095.59,1837.94 3095.59,1857.63 3040.48,1857.63 3040.48,1830.07 3064.63,1808.39 3070.63,1802.39 3167.63,1802.39
  region net GND: 3176.63,2293.39 3187.63,2293.39 3187.63,2232.39 3188.98,2228.35 3188.98,2090.55 3153.54,2090.55 3153.54,2055.12 3165.35,2043.31 3129.92,2043.31 3123.15,2050.54 3124.63,2180.39 3176.63,2232.39
  region net NetL121_1: 2520,1865 2520,2072 2511,2104 2501,2066 2501,1878 2515.32,1862.78
  region net NetL122_1: 2471,1865 2471,2072 2480,2104 2490,2066 2490,1878 2475.68,1862.78
  region net NetL132_1: 3256,1865 3256,2072 3265,2104 3275,2066 3275,1878 3260.68,1862.78
  region net NetL131_1: 3305,1865 3305,2072 3296,2104 3286,2066 3286,1878 3300.32,1862.78
  region net NetL142_1: 4041,1865 4041,2072 4050,2104 4060,2066 4060,1878 4045.68,1862.78
  region net NetL141_1: 4090,1865 4090,2072 4087,2103 4071,2063 4071,1878 4085.32,1862.78
  region net NetL152_1: 4826,1865 4826,2072 4835,2104 4845,2066 4845,1878 4830.68,1862.78
  region net NetL151_1: 4875,1865 4875,2072 4866,2104 4856,2066 4856,1878 4870.32,1862.78
  region net NetL162_1: 5611,1865 5611,2072 5620,2104 5630,2066 5630,1878 5615.68,1862.78
  region net NetL161_1: 5660,1865 5660,2072 5651,2104 5641,2066 5641,1878 5655.32,1862.78
  text "Copper top 70u" at -295,3840 h196.85
signal:
  rectangle net GND: 2425.64,1677.39 2565.64,1817.39
  rectangle net GND: 3210.63,1677.39 3350.63,1817.39
  rectangle net GND: 3995.63,1677.39 4135.63,1817.39
  rectangle net GND: 4780.63,1677.39 4920.63,1817.39
  region net +24V: 5583.14,1935.28 5583.14,1978.58 5571.33,1990.39 5543.77,1990.39 5524.09,1974.65 5531.96,1962.83 5531.96,1935.28 5533.97,1935.39
  region net +24V: 5736.69,1935.28 5738.38,1969.99 5740.62,2014.02 5689.44,1990.39 5689.44,1935.28 5691.45,1935.39
  region net +24V: 4798.14,1935.28 4798.14,1978.58 4786.33,1990.39 4758.77,1990.39 4739.09,1974.65 4746.96,1962.83 4746.96,1935.28 4748.97,1935.39
  region net +24V: 4951.69,1935.28 4953.38,1969.99 4955.62,2014.02 4904.44,1990.39 4904.44,1935.28 4906.45,1935.39
  region net +24V: 4013.14,1935.28 4013.14,1978.58 4001.33,1990.39 3973.77,1990.39 3954.09,1974.65 3961.96,1962.83 3961.96,1935.28 3963.97,1935.39
  region net +24V: 4166.69,1935.28 4168.38,1969.99 4170.62,2014.02 4119.44,1990.39 4119.44,1935.28 4121.45,1935.39
  region net +24V: 3228.14,1935.28 3228.14,1978.58 3216.33,1990.39 3188.77,1990.39 3169.09,1974.65 3176.96,1962.83 3176.96,1935.28 3178.97,1935.39
  region net +24V: 3381.69,1935.28 3383.38,1969.99 3385.62,2014.02 3334.44,1990.39 3334.44,1935.28 3336.45,1935.39
  region net +24V: 2596.69,1935.28 2598.39,1969.99 2600.63,2014.02 2549.45,1990.39 2549.45,1935.28 2551.45,1935.39
  region net +24V: 2443.15,1935.28 2443.15,1978.58 2431.34,1990.39 2403.78,1990.39 2384.09,1974.65 2391.97,1962.83 2391.97,1935.28 2393.97,1935.39
  pour cut-out: 5346.66,1997.6 ccw(c5346.66,1968.6) 5317.66,1968.6 ccw(c5346.66,1968.6) 5346.66,1939.6 ccw(c5346.66,1968.6) 5375.66,1968.6 ccw(c5346.66,1968.6)
  pour cut-out: 4563.2,1993.66 ccw(c4563.2,1964.66) 4534.2,1964.66 ccw(c4563.2,1964.66) 4563.2,1935.66 ccw(c4563.2,1964.66) 4592.2,1964.66 ccw(c4563.2,1964.66)
  pour cut-out: 5346.66,1887.37 ccw(c5346.66,1858.37) 5317.66,1858.37 ccw(c5346.66,1858.37) 5346.66,1829.37 ccw(c5346.66,1858.37) 5375.66,1858.37 ccw(c5346.66,1858.37)
  pour cut-out: 5138,1926.74 ccw(c5138,1897.74) 5109,1897.74 ccw(c5138,1897.74) 5138,1868.74 ccw(c5138,1897.74) 5167,1897.74 ccw(c5138,1897.74)
  pour cut-out: 4563.2,1887.37 ccw(c4563.2,1858.37) 4534.2,1858.37 ccw(c4563.2,1858.37) 4563.2,1829.37 ccw(c4563.2,1858.37) 4592.2,1858.37 ccw(c4563.2,1858.37)
  pour cut-out: 4358.48,1926.74 ccw(c4358.48,1897.74) 4329.48,1897.74 ccw(c4358.48,1897.74) 4358.48,1868.74 ccw(c4358.48,1897.74) 4387.48,1897.74 ccw(c4358.48,1897.74)
  pour cut-out: 3779.74,1887.37 ccw(c3779.74,1858.37) 3750.74,1858.37 ccw(c3779.74,1858.37) 3779.74,1829.37 ccw(c3779.74,1858.37) 3808.74,1858.37 ccw(c3779.74,1858.37)
  pour cut-out: 3783.67,2005.48 ccw(c3783.67,1976.48) 3754.67,1976.48 ccw(c3783.67,1976.48) 3783.67,1947.48 ccw(c3783.67,1976.48) 3812.67,1976.48 ccw(c3783.67,1976.48)
  pour cut-out: 3574.65,1925.49 ccw(c3574.65,1896.49) 3545.65,1896.49 ccw(c3574.65,1896.49) 3574.65,1867.49 ccw(c3574.65,1896.49) 3603.65,1896.49 ccw(c3574.65,1896.49)
  pour cut-out: 2992.33,1887.37 ccw(c2992.33,1858.37) 2963.33,1858.37 ccw(c2992.33,1858.37) 2992.33,1829.37 ccw(c2992.33,1858.37) 3021.33,1858.37 ccw(c2992.33,1858.37)
  pour cut-out: 2992.33,1997.6 ccw(c2992.33,1968.6) 2963.33,1968.6 ccw(c2992.33,1968.6) 2992.33,1939.6 ccw(c2992.33,1968.6) 3021.33,1968.6 ccw(c2992.33,1968.6)
  pour cut-out: 2791.55,1926.74 ccw(c2791.55,1897.74) 2762.55,1897.74 ccw(c2791.55,1897.74) 2791.55,1868.74 ccw(c2791.55,1897.74) 2820.55,1897.74 ccw(c2791.55,1897.74)
  pour cut-out: 2206.16,1888.49 ccw(c2206.16,1859.49) 2177.16,1859.49 ccw(c2206.16,1859.49) 2206.16,1830.49 ccw(c2206.16,1859.49) 2235.16,1859.49 ccw(c2206.16,1859.49)
  pour cut-out: 2206.16,1996.24 ccw(c2206.16,1967.24) 2177.16,1967.24 ccw(c2206.16,1967.24) 2206.16,1938.24 ccw(c2206.16,1967.24) 2235.16,1967.24 ccw(c2206.16,1967.24)
  pour cut-out: 3584.85,2436.49 ccw(c3584.85,2407.49) 3555.85,2407.49 ccw(c3584.85,2407.49) 3584.85,2378.49 ccw(c3584.85,2407.49) 3613.85,2407.49 ccw(c3584.85,2407.49)
  pour cut-out: 2799.85,2436.49 ccw(c2799.85,2407.49) 2770.85,2407.49 ccw(c2799.85,2407.49) 2799.85,2378.49 ccw(c2799.85,2407.49) 2828.85,2407.49 ccw(c2799.85,2407.49)
  pour cut-out: 4369.85,2436.49 ccw(c4369.85,2407.49) 4340.85,2407.49 ccw(c4369.85,2407.49) 4369.85,2378.49 ccw(c4369.85,2407.49) 4398.85,2407.49 ccw(c4369.85,2407.49)
  pour cut-out: 5154.85,2436.49 ccw(c5154.85,2407.49) 5125.85,2407.49 ccw(c5154.85,2407.49) 5154.85,2378.49 ccw(c5154.85,2407.49) 5183.85,2407.49 ccw(c5154.85,2407.49)
  pour cut-out: 5939.85,2436.49 ccw(c5939.85,2407.49) 5910.85,2407.49 ccw(c5939.85,2407.49) 5939.85,2378.49 ccw(c5939.85,2407.49) 5968.85,2407.49 ccw(c5939.85,2407.49)
  pour cut-out: 5910.85,1516.49 ccw(c5910.85,1487.49) 5881.85,1487.49 ccw(c5910.85,1487.49) 5910.85,1458.49 ccw(c5910.85,1487.49) 5939.85,1487.49 ccw(c5910.85,1487.49)
  pour cut-out: 5917.84,1925.49 ccw(c5917.84,1896.49) 5888.84,1896.49 ccw(c5917.84,1896.49) 5917.84,1867.49 ccw(c5917.84,1896.49) 5946.84,1896.49 ccw(c5917.84,1896.49)
  pour cut-out: 5776.85,1882.49 ccw(c5776.85,1853.49) 5747.85,1853.49 ccw(c5776.85,1853.49) 5776.85,1824.49 ccw(c5776.85,1853.49) 5805.85,1853.49 ccw(c5776.85,1853.49)
  pour cut-out: 5781.51,2166.26 ccw(c5781.51,2137.26) 5752.51,2137.26 ccw(c5781.51,2137.26) 5781.51,2108.26 ccw(c5781.51,2137.26) 5810.51,2137.26 ccw(c5781.51,2137.26)
  pour cut-out: 5903.56,2185.94 ccw(c5903.56,2156.94) 5874.56,2156.94 ccw(c5903.56,2156.94) 5903.56,2127.94 ccw(c5903.56,2156.94) 5932.56,2156.94 ccw(c5903.56,2156.94)
  pour cut-out: 5365.85,1506.49 ccw(c5365.85,1477.49) 5336.85,1477.49 ccw(c5365.85,1477.49) 5365.85,1448.49 ccw(c5365.85,1477.49) 5394.85,1477.49 ccw(c5365.85,1477.49)
  pour cut-out: 5365.85,1616.49 ccw(c5365.85,1587.49) 5336.85,1587.49 ccw(c5365.85,1587.49) 5365.85,1558.49 ccw(c5365.85,1587.49) 5394.85,1587.49 ccw(c5365.85,1587.49)
  pour cut-out: 5494.85,1882.49 ccw(c5494.85,1853.49) 5465.85,1853.49 ccw(c5494.85,1853.49) 5494.85,1824.49 ccw(c5494.85,1853.49) 5523.85,1853.49 ccw(c5494.85,1853.49)
  pour cut-out: 5498.05,2162.32 ccw(c5498.05,2133.32) 5469.05,2133.32 ccw(c5498.05,2133.32) 5498.05,2104.32 ccw(c5498.05,2133.32) 5527.05,2133.32 ccw(c5498.05,2133.32)
  pour cut-out: 5366.21,2135.98 ccw(c5366.21,2106.98) 5337.21,2106.98 ccw(c5366.21,2106.98) 5366.21,2077.98 ccw(c5366.21,2106.98) 5395.21,2106.98 ccw(c5366.21,2106.98)
  pour cut-out: 5125.85,1516.49 ccw(c5125.85,1487.49) 5096.85,1487.49 ccw(c5125.85,1487.49) 5125.85,1458.49 ccw(c5125.85,1487.49) 5154.85,1487.49 ccw(c5125.85,1487.49)
  pour cut-out: 5118.56,2185.94 ccw(c5118.56,2156.94) 5089.56,2156.94 ccw(c5118.56,2156.94) 5118.56,2127.94 ccw(c5118.56,2156.94) 5147.56,2156.94 ccw(c5118.56,2156.94)
  pour cut-out: 4996.51,2166.26 ccw(c4996.51,2137.26) 4967.51,2137.26 ccw(c4996.51,2137.26) 4996.51,2108.26 ccw(c4996.51,2137.26) 5025.51,2137.26 ccw(c4996.51,2137.26)
  pour cut-out: 4991.85,1882.49 ccw(c4991.85,1853.49) 4962.85,1853.49 ccw(c4991.85,1853.49) 4991.85,1824.49 ccw(c4991.85,1853.49) 5020.85,1853.49 ccw(c4991.85,1853.49)
  pour cut-out: 4713.85,1506.49 ccw(c4713.85,1477.49) 4684.85,1477.49 ccw(c4713.85,1477.49) 4713.85,1448.49 ccw(c4713.85,1477.49) 4742.85,1477.49 ccw(c4713.85,1477.49)
  pour cut-out: 4580.85,1506.49 ccw(c4580.85,1477.49) 4551.85,1477.49 ccw(c4580.85,1477.49) 4580.85,1448.49 ccw(c4580.85,1477.49) 4609.85,1477.49 ccw(c4580.85,1477.49)
  pour cut-out: 4580.85,1616.49 ccw(c4580.85,1587.49) 4551.85,1587.49 ccw(c4580.85,1587.49) 4580.85,1558.49 ccw(c4580.85,1587.49) 4609.85,1587.49 ccw(c4580.85,1587.49)
  pour cut-out: 4709.85,1882.49 ccw(c4709.85,1853.49) 4680.85,1853.49 ccw(c4709.85,1853.49) 4709.85,1824.49 ccw(c4709.85,1853.49) 4738.85,1853.49 ccw(c4709.85,1853.49)
  pour cut-out: 4713.05,2162.32 ccw(c4713.05,2133.32) 4684.05,2133.32 ccw(c4713.05,2133.32) 4713.05,2104.32 ccw(c4713.05,2133.32) 4742.05,2133.32 ccw(c4713.05,2133.32)
  pour cut-out: 4580.85,2135.49 ccw(c4580.85,2106.49) 4551.85,2106.49 ccw(c4580.85,2106.49) 4580.85,2077.49 ccw(c4580.85,2106.49) 4609.85,2106.49 ccw(c4580.85,2106.49)
  pour cut-out: 4333.56,2185.94 ccw(c4333.56,2156.94) 4304.56,2156.94 ccw(c4333.56,2156.94) 4333.56,2127.94 ccw(c4333.56,2156.94) 4362.56,2156.94 ccw(c4333.56,2156.94)
  pour cut-out: 4211.51,2166.26 ccw(c4211.51,2137.26) 4182.51,2137.26 ccw(c4211.51,2137.26) 4211.51,2108.26 ccw(c4211.51,2137.26) 4240.51,2137.26 ccw(c4211.51,2137.26)
  pour cut-out: 4206.85,1882.49 ccw(c4206.85,1853.49) 4177.85,1853.49 ccw(c4206.85,1853.49) 4206.85,1824.49 ccw(c4206.85,1853.49) 4235.85,1853.49 ccw(c4206.85,1853.49)
  pour cut-out: 4340.85,1516.49 ccw(c4340.85,1487.49) 4311.85,1487.49 ccw(c4340.85,1487.49) 4340.85,1458.49 ccw(c4340.85,1487.49) 4369.85,1487.49 ccw(c4340.85,1487.49)
  pour cut-out: 3795.85,1506.49 ccw(c3795.85,1477.49) 3766.85,1477.49 ccw(c3795.85,1477.49) 3795.85,1448.49 ccw(c3795.85,1477.49) 3824.85,1477.49 ccw(c3795.85,1477.49)
  pour cut-out: 3795.85,1616.49 ccw(c3795.85,1587.49) 3766.85,1587.49 ccw(c3795.85,1587.49) 3795.85,1558.49 ccw(c3795.85,1587.49) 3824.85,1587.49 ccw(c3795.85,1587.49)
  pour cut-out: 3924.85,1882.49 ccw(c3924.85,1853.49) 3895.85,1853.49 ccw(c3924.85,1853.49) 3924.85,1824.49 ccw(c3924.85,1853.49) 3953.85,1853.49 ccw(c3924.85,1853.49)
  pour cut-out: 3928.05,2162.32 ccw(c3928.05,2133.32) 3899.05,2133.32 ccw(c3928.05,2133.32) 3928.05,2104.32 ccw(c3928.05,2133.32) 3957.05,2133.32 ccw(c3928.05,2133.32)
  pour cut-out: 3795.85,2135.49 ccw(c3795.85,2106.49) 3766.85,2106.49 ccw(c3795.85,2106.49) 3795.85,2077.49 ccw(c3795.85,2106.49) 3824.85,2106.49 ccw(c3795.85,2106.49)
  pour cut-out: 3548.56,2185.94 ccw(c3548.56,2156.94) 3519.56,2156.94 ccw(c3548.56,2156.94) 3548.56,2127.94 ccw(c3548.56,2156.94) 3577.56,2156.94 ccw(c3548.56,2156.94)
  pour cut-out: 3426.51,2166.26 ccw(c3426.51,2137.26) 3397.51,2137.26 ccw(c3426.51,2137.26) 3426.51,2108.26 ccw(c3426.51,2137.26) 3455.51,2137.26 ccw(c3426.51,2137.26)
  pour cut-out: 3421.85,1882.49 ccw(c3421.85,1853.49) 3392.85,1853.49 ccw(c3421.85,1853.49) 3421.85,1824.49 ccw(c3421.85,1853.49) 3450.85,1853.49 ccw(c3421.85,1853.49)
  pour cut-out: 3555.85,1511.49 ccw(c3555.85,1482.49) 3526.85,1482.49 ccw(c3555.85,1482.49) 3555.85,1453.49 ccw(c3555.85,1482.49) 3584.85,1482.49 ccw(c3555.85,1482.49)
  pour cut-out: 3143.85,1506.49 ccw(c3143.85,1477.49) 3114.85,1477.49 ccw(c3143.85,1477.49) 3143.85,1448.49 ccw(c3143.85,1477.49) 3172.85,1477.49 ccw(c3143.85,1477.49)
  pour cut-out: 3010.85,1506.49 ccw(c3010.85,1477.49) 2981.85,1477.49 ccw(c3010.85,1477.49) 3010.85,1448.49 ccw(c3010.85,1477.49) 3039.85,1477.49 ccw(c3010.85,1477.49)
  pour cut-out: 3010.85,1616.49 ccw(c3010.85,1587.49) 2981.85,1587.49 ccw(c3010.85,1587.49) 3010.85,1558.49 ccw(c3010.85,1587.49) 3039.85,1587.49 ccw(c3010.85,1587.49)
  pour cut-out: 3139.85,1882.49 ccw(c3139.85,1853.49) 3110.85,1853.49 ccw(c3139.85,1853.49) 3139.85,1824.49 ccw(c3139.85,1853.49) 3168.85,1853.49 ccw(c3139.85,1853.49)
  pour cut-out: 3010.85,2135.49 ccw(c3010.85,2106.49) 2981.85,2106.49 ccw(c3010.85,2106.49) 3010.85,2077.49 ccw(c3010.85,2106.49) 3039.85,2106.49 ccw(c3010.85,2106.49)
  pour cut-out: 3143.05,2162.32 ccw(c3143.05,2133.32) 3114.05,2133.32 ccw(c3143.05,2133.32) 3143.05,2104.32 ccw(c3143.05,2133.32) 3172.05,2133.32 ccw(c3143.05,2133.32)
  pour cut-out: 2763.56,2185.94 ccw(c2763.56,2156.94) 2734.56,2156.94 ccw(c2763.56,2156.94) 2763.56,2127.94 ccw(c2763.56,2156.94) 2792.56,2156.94 ccw(c2763.56,2156.94)
  pour cut-out: 2636.85,1882.49 ccw(c2636.85,1853.49) 2607.85,1853.49 ccw(c2636.85,1853.49) 2636.85,1824.49 ccw(c2636.85,1853.49) 2665.85,1853.49 ccw(c2636.85,1853.49)
  pour cut-out: 2770.85,1516.49 ccw(c2770.85,1487.49) 2741.85,1487.49 ccw(c2770.85,1487.49) 2770.85,1458.49 ccw(c2770.85,1487.49) 2799.85,1487.49 ccw(c2770.85,1487.49)
  pour cut-out: 2358.85,1506.49 ccw(c2358.85,1477.49) 2329.85,1477.49 ccw(c2358.85,1477.49) 2358.85,1448.49 ccw(c2358.85,1477.49) 2387.85,1477.49 ccw(c2358.85,1477.49)
  pour cut-out: 2225.85,1506.49 ccw(c2225.85,1477.49) 2196.85,1477.49 ccw(c2225.85,1477.49) 2225.85,1448.49 ccw(c2225.85,1477.49) 2254.85,1477.49 ccw(c2225.85,1477.49)
  pour cut-out: 2225.85,1616.49 ccw(c2225.85,1587.49) 2196.85,1587.49 ccw(c2225.85,1587.49) 2225.85,1558.49 ccw(c2225.85,1587.49) 2254.85,1587.49 ccw(c2225.85,1587.49)
  pour cut-out: 2354.85,1882.49 ccw(c2354.85,1853.49) 2325.85,1853.49 ccw(c2354.85,1853.49) 2354.85,1824.49 ccw(c2354.85,1853.49) 2383.85,1853.49 ccw(c2354.85,1853.49)
  pour cut-out: 2641.51,2166.26 ccw(c2641.51,2137.26) 2612.51,2137.26 ccw(c2641.51,2137.26) 2641.51,2108.26 ccw(c2641.51,2137.26) 2670.51,2137.26 ccw(c2641.51,2137.26)
  pour cut-out: 2358.05,2162.32 ccw(c2358.05,2133.32) 2329.05,2133.32 ccw(c2358.05,2133.32) 2358.05,2104.32 ccw(c2358.05,2133.32) 2387.05,2133.32 ccw(c2358.05,2133.32)
  pour cut-out: 2225.85,2135.49 ccw(c2225.85,2106.49) 2196.85,2106.49 ccw(c2225.85,2106.49) 2225.85,2077.49 ccw(c2225.85,2106.49) 2254.85,2106.49 ccw(c2225.85,2106.49)
  pour cut-out: -160,1908.15 cw(c-60,1908.15) -60,2008.15 165,2008.15 215,2058.15 215,2088.15 cw(c315,2088.15) 315,2188.15 325,2188.15 cw(c325,2088.15) 425,2088.15 425,2001.43 cw(c356.72,2001.43) 405,1953.15 279.29,1827.44 cw(c208.58,1898.15) 208.58,1798.15 -60,1798.15 cw(c-60,1898.15) -160,1898.15
  pour cut-out: 556.22,2714.06 ccw(c556.22,2639.06) 481.22,2639.06 ccw(c556.22,2639.06) 556.22,2564.06 ccw(c556.22,2639.06) 631.22,2639.06 ccw(c556.22,2639.06)
  pour cut-out: 792.44,2155 ccw(c792.44,2080) 717.44,2080 ccw(c792.44,2080) 792.44,2005 ccw(c792.44,2080) 867.44,2080 ccw(c792.44,2080)
  pour cut-out: 1000,2536 ccw(c1000,2461) 925,2461 ccw(c1000,2461) 1000,2386 ccw(c1000,2461) 1075,2461 ccw(c1000,2461)
  pour cut-out: 1200,2536 ccw(c1200,2461) 1125,2461 ccw(c1200,2461) 1200,2386 ccw(c1200,2461) 1275,2461 ccw(c1200,2461)
  pour cut-out: 1400,2536 ccw(c1400,2461) 1325,2461 ccw(c1400,2461) 1400,2386 ccw(c1400,2461) 1475,2461 ccw(c1400,2461)
  pour cut-out: 1600,2536 ccw(c1600,2461) 1525,2461 ccw(c1600,2461) 1600,2386 ccw(c1600,2461) 1675,2461 ccw(c1600,2461)
  pour cut-out: 1800,2536 ccw(c1800,2461) 1725,2461 ccw(c1800,2461) 1800,2386 ccw(c1800,2461) 1875,2461 ccw(c1800,2461)
  pour cut-out: 2000,2536 ccw(c2000,2461) 1925,2461 ccw(c2000,2461) 2000,2386 ccw(c2000,2461) 2075,2461 ccw(c2000,2461)
  pour cut-out: 5452.85,1455.49 ccw(c5452.85,1426.49) 5423.85,1426.49 ccw(c5452.85,1426.49) 5452.85,1397.49 ccw(c5452.85,1426.49) 5481.85,1426.49 ccw(c5452.85,1426.49)
  pour cut-out: 3882.1,1407.05 ccw(c3882.1,1378.05) 3853.1,1378.05 ccw(c3882.1,1378.05) 3882.1,1349.05 ccw(c3882.1,1378.05) 3911.1,1378.05 ccw(c3882.1,1378.05)
  text "Copper inner1 35u" at -295,3565 h196.85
